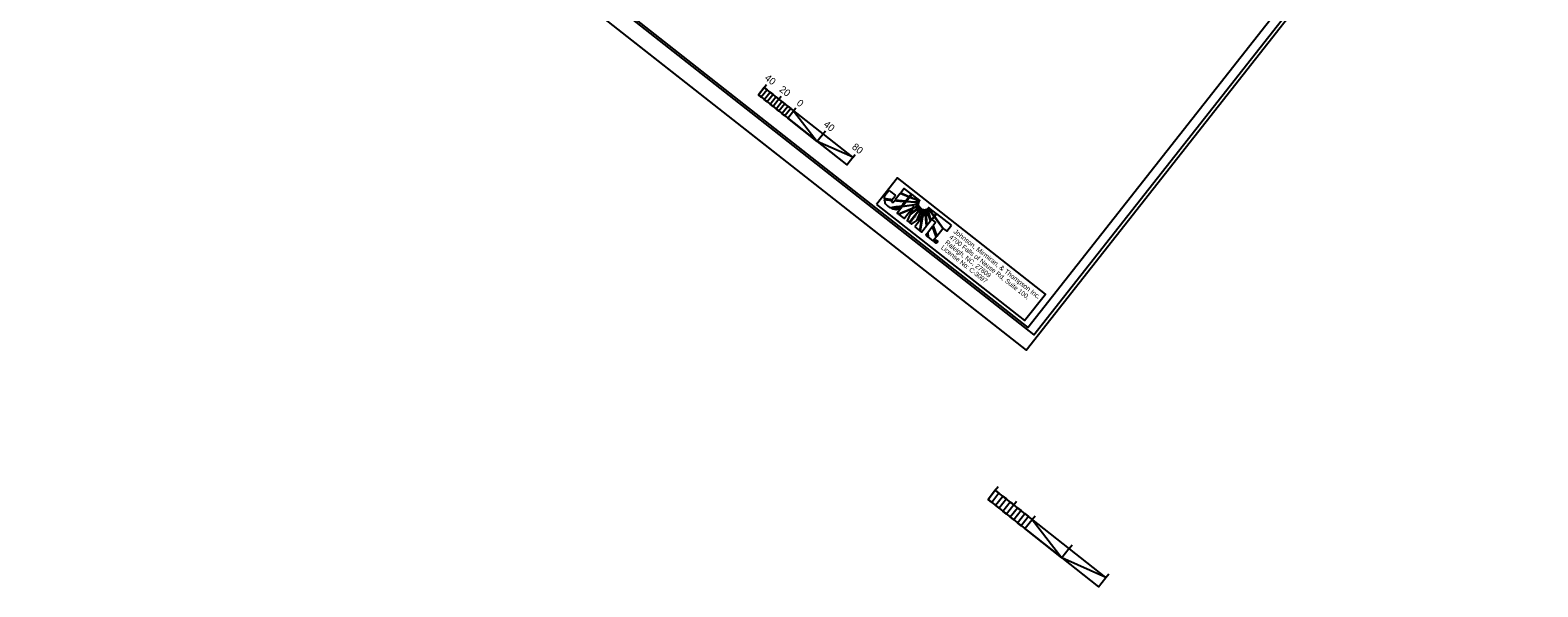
# Model space of a CAD drawing. Extents: x 556999 to 558602, y 505955 to 507732.
# Drawn here: x 556999 to 558602, y 505955 to 506548 of the extents above; entities that cross this region are included whole.
import ezdxf

# ---------------------------------------------------------------- set-up
doc = ezdxf.new("R2010")
doc.units = 0
for name, color, linetype in [('Prop Dimension', 7, 'Continuous'), ('Sheet Border Standard 30in CELL', 7, 'Continuous'), ('Sheet Cutting Line CELL', 7, 'Continuous'), ('Sheet Data Field CELL', 7, 'Continuous'), ('Sheet Plot Border Inside CELL', 7, 'Continuous'), ('Sheet Plot Border Outside CELL', 7, 'Continuous'), ('Sheet Title CELL', 7, 'Continuous')]:
    doc.layers.add(name, color=color, linetype=linetype)

msp = doc.modelspace()

# ---------------------------------------------------------------- linework, layer by layer
at = {"layer": 'Prop Dimension'}
for p, q in [((557924.2, 506373.6), (557918.8, 506366.8)), ((557933.2, 506369.9), (557924.2, 506373.6)), ((557928.5, 506379.1), (557924.7, 506374.2)), ((557924.7, 506374.2), (557933.6, 506370.5)), ((557935.9, 506373.3), (557928.5, 506379.1)), ((557933.6, 506370.5), (557935.9, 506373.3)), ((557936.7, 506372.7), (557934.6, 506370.1)), ((557944.9, 506366.2), (557936.7, 506372.7)), ((557918.8, 506366.8), (557929.9, 506365.7)), ((557926.3, 506359.5), (557921, 506352.8)), ((557922.3, 506351.9), (557936.8, 506358)), ((557936, 506357), (557922.8, 506351.4)), ((557941, 506361.6), (557926.3, 506359.5)), ((557930.5, 506364.9), (557926.9, 506360.3)), ((557926.9, 506360.3), (557941, 506362.3)), ((557928.3, 506347.1), (557936, 506357)), ((557929.9, 506365.7), (557933.2, 506369.9)), ((557940.1, 506364), (557930.5, 506364.9)), ((557934.1, 506369.5), (557931, 506365.5)), ((557931, 506365.5), (557939.3, 506364.7)), ((557941.7, 506366.4), (557934.1, 506369.5)), ((557942.8, 506357.3), (557934.5, 506351)), ((557934.6, 506370.1), (557942.1, 506367)), ((557935, 506352.2), (557942.7, 506358)), ((557937.3, 506357.5), (557935, 506352.2)), ((557936.8, 506358), (557938.3, 506360)), ((557941.8, 506359.4), (557937.3, 506357.5)), ((557938.3, 506360), (557937.7, 506358.4)), ((557937.7, 506358.4), (557941.4, 506360)), ((557939.3, 506364.7), (557944.3, 506364.8)), ((557944, 506363.2), (557940.1, 506364)), ((557941, 506362.3), (557944, 506363.2)), ((557944.2, 506361.6), (557941, 506361.6)), ((557941.4, 506360), (557944.2, 506361.6)), ((557941.4, 506352.8), (557945.7, 506358.9)), ((557944.3, 506364.8), (557941.7, 506366.4)), ((557944.7, 506360.1), (557941.8, 506359.4)), ((557946.9, 506357.9), (557941.9, 506352.4)), ((557942.1, 506367), (557944.9, 506366.2)), ((557942.7, 506358), (557944.7, 506360.1)), ((557945.7, 506358.9), (557942.8, 506357.3)), ((557946, 506354.8), (557946.9, 506357.9)), ((557948.3, 506357.3), (557946.7, 506354.8)), ((557948.3, 506354.3), (557948.3, 506357.3)), ((557949.9, 506357.1), (557948.9, 506354.1)), ((557950.6, 506354.1), (557949.9, 506357.1)), ((557951.4, 506357.3), (557951.3, 506354.2)), ((557953.2, 506353.7), (557951.4, 506357.3)), ((557953, 506358), (557954.1, 506353)), ((557955, 506355.9), (557953, 506358)), ((557962.5, 506352.4), (557954.3, 506358.9)), ((557954.3, 506358.9), (557955.6, 506356.3)), ((557955.6, 506356.3), (557960.4, 506349.8)), ((557921, 506352.8), (557922.3, 506351.9)), ((557922.8, 506351.4), (557928.3, 506347.1)), ((557934.5, 506351), (557931.7, 506344.6)), ((557931.7, 506344.6), (557933.7, 506343)), ((557933.7, 506343), (557941.4, 506352.8)), ((557941.9, 506352.4), (557934.2, 506342.6)), ((557934.2, 506342.6), (557936.3, 506341)), ((557936.3, 506341), (557941.8, 506345)), ((557947.2, 506347.9), (557939.7, 506338.3)), ((557941.8, 506345), (557946, 506354.8)), ((557946.7, 506354.8), (557942.8, 506345.8)), ((557942.8, 506345.8), (557947.5, 506349.4)), ((557945, 506334.1), (557947.2, 506347.9)), ((557948, 506348.9), (557945.5, 506333.6)), ((557947.5, 506349.4), (557948.3, 506354.3)), ((557949.7, 506351.1), (557948, 506348.9)), ((557948.9, 506354.1), (557948.2, 506349.9)), ((557948.2, 506349.9), (557949.7, 506351.1)), ((557952, 506339.2), (557950.6, 506354.1)), ((557951.3, 506354.2), (557952.6, 506340)), ((557952.6, 506340), (557956.3, 506344.7)), ((557956.3, 506344.7), (557953.2, 506353.7)), ((557954.1, 506353), (557956.8, 506345.4)), ((557960, 506349.2), (557955, 506355.9)), ((557956.8, 506345.4), (557960, 506349.2)), ((557960.4, 506348.6), (557958.1, 506345.6)), ((557958.1, 506345.6), (557961.8, 506342.7)), ((557961.8, 506342.7), (557959.1, 506339.1)), ((557960.4, 506349.8), (557962.5, 506352.4)), ((557960.4, 506348.7), (557960.4, 506348.6)), ((557969.3, 506336.4), (557960.4, 506348.7)), ((557963.1, 506352), (557960.8, 506349.2)), ((557960.8, 506349.2), (557960.8, 506349.1)), ((557960.8, 506349.1), (557970.3, 506336.1)), ((557978.5, 506339.9), (557963.1, 506352)), ((557939.7, 506338.3), (557945, 506334.1)), ((557945.5, 506333.6), (557946.8, 506332.6)), ((557946.8, 506332.6), (557952, 506339.2)), ((557952.9, 506331.2), (557951.2, 506329.2)), ((557951.2, 506329.2), (557953.1, 506327.7)), ((557953.1, 506327.7), (557952.9, 506331.2)), ((557958.6, 506338.5), (557953.4, 506331.9)), ((557953.4, 506331.9), (557953.9, 506327.1)), ((557953.9, 506327.1), (557958.9, 506323.2)), ((557962.5, 506327.7), (557958.6, 506338.5)), ((557958.9, 506323.2), (557962.5, 506327.7)), ((557959.1, 506339.1), (557962.9, 506328.3)), ((557962.9, 506328.3), (557969.3, 506336.4)), ((557970.3, 506336.1), (557973.6, 506333.5)), ((557973.6, 506333.5), (557978.5, 506339.9)), ((557961.5, 506321.5), (557961.3, 506321.3)), ((557961.3, 506321.3), (557961.5, 506321.5)), ((557961.3, 506321.3), (557961.3, 506321.3)), ((557961.4, 506322.3), (557962.2, 506323.5)), ((557961.6, 506322.1), (557961.4, 506322.3)), ((557961.5, 506321.5), (557961.5, 506321.5)), ((557962, 506322.6), (557961.6, 506322.1)), ((557962.2, 506322.4), (557962, 506322.6)), ((557962.3, 506323.1), (557962.1, 506322.8)), ((557962.1, 506322.8), (557962.3, 506322.6)), ((557962.2, 506323.5), (557962.7, 506323.1)), ((557962.3, 506322.6), (557962.2, 506322.4)), ((557962.2, 506322.4), (557962.3, 506322.6)), ((557962.2, 506322.4), (557962.2, 506322.4)), ((557962.5, 506322.9), (557962.3, 506323.1)), ((557962.3, 506322.6), (557962.3, 506322.6)), ((557962.7, 506323.1), (557962.5, 506322.9)), ((557962.5, 506322.9), (557962.7, 506323.1)), ((557962.6, 506322.9), (557962.5, 506322.9)), ((557962.7, 506323.1), (557962.8, 506323)), ((557963.2, 506323.8), (557963, 506323.5)), ((557963, 506323.5), (557963.2, 506323.8))]:
    msp.add_line(p, q, dxfattribs=at)
msp.add_lwpolyline([(557899, 506362), (558056.2, 506238.4), (558078.5, 506266.7), (557921.3, 506390.4)], close=True, dxfattribs=at)
for points in [[(557918.8, 506366.8), (557929.9, 506365.7), (557933.2, 506369.9), (557924.2, 506373.6), (557918.8, 506366.8)], [(557924.7, 506374.2), (557933.6, 506370.5), (557935.9, 506373.3), (557928.5, 506379.1), (557924.7, 506374.2)], [(557942.1, 506367), (557944.9, 506366.2), (557936.7, 506372.7), (557934.6, 506370.1), (557942.1, 506367)], [(557944.2, 506361.6), (557941, 506361.6), (557926.3, 506359.5), (557921, 506352.8), (557922.3, 506351.9), (557936.8, 506358), (557938.3, 506360), (557937.7, 506358.4), (557941.4, 506360), (557944.2, 506361.6)], [(557922.8, 506351.4), (557928.3, 506347.1), (557936, 506357), (557922.8, 506351.4)], [(557930.5, 506364.9), (557926.9, 506360.3), (557941, 506362.3), (557944, 506363.2), (557940.1, 506364), (557930.5, 506364.9)], [(557934.1, 506369.5), (557931, 506365.5), (557939.3, 506364.7), (557944.3, 506364.8), (557941.7, 506366.4), (557934.1, 506369.5)], [(557942.8, 506357.3), (557934.5, 506351), (557931.7, 506344.6), (557933.7, 506343), (557941.4, 506352.8), (557945.7, 506358.9), (557942.8, 506357.3)], [(557946.9, 506357.9), (557941.9, 506352.4), (557934.2, 506342.6), (557936.3, 506341), (557941.8, 506345), (557946, 506354.8), (557946.9, 506357.9)], [(557944.7, 506360.1), (557941.8, 506359.4), (557937.3, 506357.5), (557935, 506352.2), (557942.7, 506358), (557944.7, 506360.1)], [(557948.3, 506357.3), (557946.7, 506354.8), (557942.8, 506345.8), (557947.5, 506349.4), (557948.3, 506354.3), (557948.3, 506357.3)], [(557949.9, 506357.1), (557948.9, 506354.1), (557948.2, 506349.9), (557949.7, 506351.1), (557948, 506348.9), (557945.5, 506333.6), (557946.8, 506332.6), (557952, 506339.2), (557950.6, 506354.1), (557949.9, 506357.1)], [(557951.4, 506357.3), (557951.3, 506354.2), (557952.6, 506340), (557956.3, 506344.7), (557953.2, 506353.7), (557951.4, 506357.3)], [(557953, 506358), (557954.1, 506353), (557956.8, 506345.4), (557960, 506349.2), (557955, 506355.9), (557953, 506358)], [(557955.6, 506356.3), (557960.4, 506349.8), (557962.5, 506352.4), (557954.3, 506358.9), (557955.6, 506356.3)], [(557939.7, 506338.3), (557945, 506334.1), (557947.2, 506347.9), (557939.7, 506338.3)], [(557960.4, 506348.7), (557960.4, 506348.6), (557958.1, 506345.6), (557961.8, 506342.7), (557959.1, 506339.1), (557962.9, 506328.3), (557969.3, 506336.4), (557960.4, 506348.7)], [(557978.5, 506339.9), (557963.1, 506352), (557960.8, 506349.2), (557960.8, 506349.1), (557970.3, 506336.1), (557973.6, 506333.5), (557978.5, 506339.9)], [(557951.2, 506329.2), (557951.2, 506329.2), (557953.1, 506327.7), (557952.9, 506331.2), (557951.2, 506329.2)], [(557958.6, 506338.5), (557953.4, 506331.9), (557953.9, 506327.1), (557958.9, 506323.2), (557962.5, 506327.7), (557958.6, 506338.5), (557958.6, 506338.5)], [(557962.5, 506321.9), (557962.5, 506321.8), (557962.4, 506321.7), (557962.4, 506321.7), (557962.3, 506321.6), (557962.1, 506321.7)]]:
    msp.add_lwpolyline(points, dxfattribs=at)
for points, degree in [([(557919.2, 506371.6), (557919.2, 506371.6), (557912.4, 506376.9), (557912.4, 506376.9), (557912.4, 506376.9), (557909, 506372.7), (557909, 506372.7), (557909, 506372.7), (557908.7, 506372.2), (557908.7, 506372.2), (557907.6, 506370.9), (557907.2, 506369.5), (557907.3, 506368), (557907.3, 506368), (557915.6, 506367), (557915.7, 506367.1), (557915.7, 506367.1), (557919.2, 506371.6), (557919.2, 506371.6)], 3), ([(557915.4, 506364.6), (557915, 506365), (557914.8, 506365.5), (557915.3, 506366.4), (557915.3, 506366.4), (557907.5, 506367.3), (557907.5, 506367.3), (557907.7, 506364.3), (557909.5, 506361.3), (557911.7, 506359.5), (557912.3, 506359.1), (557912.8, 506358.8), (557913.5, 506358.5), (557913.5, 506358.5), (557925.5, 506360.1), (557925.5, 506360.1), (557925.5, 506360.1), (557929.4, 506365.1), (557929.4, 506365.1), (557929.4, 506365.1), (557918.4, 506366.2), (557918.4, 506366.2), (557916.9, 506364.3), (557916.1, 506364.2), (557915.4, 506364.6)], 3), ([(557915.4, 506364.6), (557915, 506365), (557914.8, 506365.5), (557915.3, 506366.4), (557915.3, 506366.4), (557907.5, 506367.3), (557907.5, 506367.3), (557907.7, 506364.3), (557909.5, 506361.3), (557911.7, 506359.5), (557912.3, 506359.1), (557912.8, 506358.8), (557913.5, 506358.5), (557913.5, 506358.5), (557925.5, 506360.1), (557925.5, 506360.1), (557925.5, 506360.1), (557929.4, 506365.1), (557929.4, 506365.1), (557929.4, 506365.1), (557918.4, 506366.2), (557918.4, 506366.2), (557916.9, 506364.3), (557916.1, 506364.2), (557915.4, 506364.6)], 3), ([(557924.9, 506359.3), (557924.9, 506359.3), (557914.5, 506357.9), (557914.5, 506357.9), (557917.9, 506356.4), (557922.1, 506356.1), (557924.9, 506359.3)], 3), ([(557961.3, 506321.3), (557960.9, 506321.6), (557960.7, 506321.9), (557960.7, 506322.4), (557960.6, 506322.8), (557960.7, 506323.2), (557961, 506323.5), (557961.3, 506323.9), (557961.6, 506324.1), (557962.1, 506324.1), (557962.5, 506324.1), (557962.9, 506324), (557963.2, 506323.8)], 3), ([(557963, 506323.5), (557962.8, 506323.8), (557962.4, 506323.8), (557962.1, 506323.8), (557961.8, 506323.8), (557961.5, 506323.6), (557961.2, 506323.3), (557961, 506323.1), (557960.9, 506322.7), (557961, 506322.4), (557961, 506322), (557961.2, 506321.8), (557961.5, 506321.5)], 3), ([(557963.5, 506321.6), (557963.2, 506321.2), (557962.9, 506321), (557962.5, 506320.9), (557962, 506320.9), (557961.6, 506321), (557961.3, 506321.3)], 3), ([(557961.5, 506321.5), (557961.8, 506321.3), (557962.1, 506321.2), (557962.4, 506321.3), (557962.8, 506321.3), (557963, 506321.5), (557963.3, 506321.7), (557963.5, 506322), (557963.6, 506322.3), (557963.5, 506322.7), (557963.5, 506323), (557963.3, 506323.3), (557963, 506323.5)], 3), ([(557962.1, 506321.7), (557962.1, 506321.8), (557962.2, 506321.9), (557962.2, 506322), (557962.3, 506322.1), (557962.3, 506322.2), (557962.3, 506322.2)], 3), ([(557962.3, 506322.2), (557962.3, 506322.3), (557962.3, 506322.3), (557962.2, 506322.4)], 2), ([(557962.3, 506322.6), (557962.5, 506322.5), (557962.6, 506322.5), (557962.7, 506322.6), (557962.7, 506322.6), (557962.7, 506322.7), (557962.6, 506322.9)], 3), ([(557962.6, 506322.2), (557962.6, 506322.1), (557962.6, 506322), (557962.5, 506321.9)], 2), ([(557962.8, 506323), (557963.1, 506322.8), (557963.1, 506322.6), (557962.9, 506322.4), (557962.9, 506322.3), (557962.7, 506322.2), (557962.6, 506322.2)], 3), ([(557963.2, 506323.8), (557963.6, 506323.5), (557963.8, 506323.1), (557963.8, 506322.7), (557963.9, 506322.3), (557963.8, 506321.9), (557963.5, 506321.6)], 3)]:
    msp.add_open_spline(points, degree=degree, dxfattribs=at)
at = {"layer": 'Sheet Border Standard 30in CELL'}
msp.add_lwpolyline([(558579, 506891.5), (557635.7, 507633.3), (557116.5, 506973), (558059.7, 506231.2)], close=True, dxfattribs=at)
at = {"layer": 'Sheet Cutting Line CELL'}
msp.add_line((556999.1, 507039.9), (558058.1, 506207.1), dxfattribs=at)
at = {"layer": 'Sheet Data Field CELL'}
for p, q in [((557779.5, 506486.6), (557782, 506489.7)), ((557795.2, 506474.2), (557797.6, 506477.3)), ((557873.6, 506412.1), (557876.1, 506415.3)), ((558025.2, 506057.9), (558028.3, 506061.8)), ((558044.8, 506042.4), (558047.9, 506046.3)), ((558103.7, 505995.9), (558106.8, 505999.8)), ((558142.9, 505964.9), (558146, 505968.8))]:
    msp.add_line(p, q, dxfattribs=at)
at = {"layer": 'Sheet Plot Border Inside CELL'}
msp.add_lwpolyline([(558588.1, 506886.9), (557540.2, 507711), (557018.4, 507047.5), (558066.3, 506223.4)], close=True, dxfattribs=at)
at = {"layer": 'Sheet Plot Border Outside CELL'}
msp.add_lwpolyline([(558602.1, 506898.8), (557543.1, 507731.6), (556999.1, 507039.9), (558058.1, 506207.1)], close=True, dxfattribs=at)
at = {"layer": 'Sheet Title CELL'}
for p, q in [((557779.5, 506486.6), (557773.3, 506478.7)), ((557779.5, 506486.6), (557781.9, 506489.7)), ((557873.6, 506412.2), (557779.5, 506486.6)), ((557773.3, 506478.7), (557867.4, 506404.3)), ((557795.1, 506474.2), (557797.6, 506477.3)), ((557801.4, 506469.2), (557795.2, 506461.4)), ((557810.8, 506461.8), (557813.3, 506464.9)), ((557844.7, 506440.1), (557836, 506429.1)), ((557867.4, 506404.3), (557873.6, 506412.2)), ((557873.6, 506412.2), (557876.1, 506415.3)), ((558025.2, 506057.9), (558017.5, 506048.1)), ((558025.2, 506057.9), (558028.3, 506061.8)), ((558142.9, 505964.9), (558025.2, 506057.9)), ((558017.5, 506048.1), (558135.1, 505955.1)), ((558044.8, 506042.4), (558047.9, 506046.3)), ((558052.7, 506036.2), (558044.9, 506026.4)), ((558064.4, 506026.9), (558067.5, 506030.8)), ((558103.7, 505995.9), (558095.9, 505986.1)), ((558103.7, 505995.9), (558106.8, 505999.8)), ((558135.1, 505955.1), (558142.9, 505964.9)), ((558142.9, 505964.9), (558146, 505968.8))]:
    msp.add_line(p, q, dxfattribs=at)
for points in [[(557779.5, 506486.6), (557782.6, 506484.1), (557776.4, 506476.2), (557773.3, 506478.7)], [(557785.7, 506481.6), (557788.9, 506479.1), (557782.7, 506471.3), (557779.5, 506473.8)], [(557792, 506476.6), (557795.1, 506474.2), (557789, 506466.3), (557785.8, 506468.8)], [(557798.3, 506471.7), (557801.4, 506469.2), (557795.2, 506461.4), (557792.1, 506463.8)], [(557804.6, 506466.7), (557807.7, 506464.2), (557801.5, 506456.4), (557798.4, 506458.9)], [(557810.8, 506461.8), (557836, 506429.1), (557804.6, 506453.9)], [(557873.6, 506412.2), (557836, 506429.1), (557867.4, 506404.3)], [(558025.2, 506057.9), (558029.1, 506054.8), (558021.4, 506045), (558017.5, 506048.1)], [(558033.1, 506051.7), (558037, 506048.6), (558029.2, 506038.8), (558025.3, 506041.9)], [(558040.9, 506045.5), (558044.8, 506042.4), (558037.1, 506032.6), (558033.2, 506035.7)], [(558048.7, 506039.3), (558052.7, 506036.2), (558044.9, 506026.4), (558041, 506029.5)], [(558056.6, 506033.1), (558060.5, 506030), (558052.8, 506020.2), (558048.8, 506023.3)], [(558064.4, 506026.9), (558095.9, 505986.1), (558056.7, 506017.1)], [(558142.9, 505964.9), (558095.9, 505986.1), (558135.1, 505955.1)]]:
    msp.add_lwpolyline(points, close=True, dxfattribs=at)

# ---------------------------------------------------------------- texts
at = {"layer": 'Prop Dimension'}
for s, height, rotation, p in [('www.jmt.com', 1.241, 231.8181, (557941.6, 506351)), ('Raleigh, NC, 27609', 4.965, 321.8181, (557971.3, 506320.7)), ('4700 Falls of Neuse Rd, Suite 100, ', 4.965, 321.8181, (557975.7, 506326.3)), ('Johnson, Mirmiran, & Thompson Inc.', 5.111, 321.8181, (557980.3, 506332.2)), ('License No: C-3097', 4.965, 321.8181, (557966.9, 506315.2))]:
    msp.add_text(s, height=height, rotation=rotation, dxfattribs=at).set_placement(p)
at = {"layer": 'Sheet Title CELL'}
for s, p in [('40', (557779.4, 506495.4)), ('20', (557795, 506483.1)), ('0', (557813.3, 506468.6)), ('40', (557842, 506445.9)), ('80', (557872.2, 506422))]:
    msp.add_text(s, height=7.5, rotation=321.6714, dxfattribs=at).set_placement(p)

doc.saveas('drawing.dxf')
